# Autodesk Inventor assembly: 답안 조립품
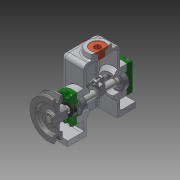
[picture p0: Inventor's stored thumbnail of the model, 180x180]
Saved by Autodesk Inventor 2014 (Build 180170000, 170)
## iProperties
Created: 2016-02
Part Number: 답안 조립품
Document SubType Name: Assembly
Designer: 703-6
Author: 703-6
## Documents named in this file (14)
- C:\Users\703-6\Desktop\460212V1022\답안 조립품.iam
- C:\Users\703-6\Desktop\460212V1022\답안부품.ipt
- C:\Users\703-6\Desktop\460212V1022\공용부품\뒤커버.ipt
- C:\Users\703-6\Desktop\460212V1022\공용부품\베어링 12 x 32 x 10.ipt
- C:\Users\703-6\Desktop\460212V1022\공용부품\편심축.ipt
- C:\Users\703-6\Desktop\460212V1022\공용부품\링크.ipt
- C:\Users\703-6\Desktop\460212V1022\공용부품\앞커버.ipt
- C:\Users\703-6\Desktop\460212V1022\공용부품\오일실 12 25 7.ipt
- C:\Users\703-6\Desktop\460212V1022\공용부품\키 4 x 4 x 10.ipt
- C:\Users\703-6\Desktop\460212V1022\공용부품\부시.ipt
- C:\Users\703-6\Desktop\460212V1022\공용부품\V벨트풀리.ipt
- C:\Users\703-6\Desktop\460212V1022\공용부품\핀 5 x 18.ipt
- C:\Users\703-6\Desktop\460212V1022\공용부품\볼트 M4 x 12.ipt
- C:\Users\703-6\Desktop\460212V1022\공용부품\고정핀 1.2 x 10.ipt
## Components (7 placed, 4 different names)
1. V벨트풀리:1
2. 핀 5 x 18:1
3. 고정핀 1.2 x 10:1
4. ISO 4762 M4 x 12:1
5. ISO 4762 M4 x 12:2
6. ISO 4762 M4 x 12:3
7. ISO 4762 M4 x 12:4
